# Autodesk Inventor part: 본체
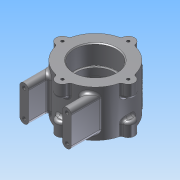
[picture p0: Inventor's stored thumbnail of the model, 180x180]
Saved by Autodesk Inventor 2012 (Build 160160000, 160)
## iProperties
Created: 2015-03
Part Number: 본체
Material: Default
Document SubType Name: Modeling
Designer: net
Density: 1 g/cm^3
Author: net
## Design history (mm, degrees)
sketch "스케치1"
  geometry: C1 r 37 at (0, 0); 1 further point
  constraints: 1 centre point, 1 coincident
  dimensions: "d0" = 74 diameter of C1
extrude "돌출1" new body sketch "스케치1" distance "d1" = 52; taper "d2" = 0 deg
hole "구멍1" diameter "d5" = 42; stored, may be unused: countersink angle "d9" = 90 deg, drill point angle "d11" = 0 deg; dims "d3" = 10, "d4" = 10, "d6" = 6, "d7" = 47, "d8" = 22, "d10" = 30
hole "구멍2" diameter "d14" = 47; stored, may be unused: countersink angle "d18" = 90 deg, drill point angle "d20" = 0 deg; dims "d12" = 10, "d13" = 10, "d15" = 6, "d16" = 47, "d17" = 22, "d19" = 22
sketch "스케치2"
  geometry: C1 r 23.5 at (0, 0) reference; C2 r 7 at (0, 37); 1 further point
  constraints: 1 centre point, 1 coincident, 1 vertical alignment
  dimensions: "d21" = 37 distance of point (0, 37) C1.centre; "d22" = 14 diameter of C2
extrude "돌출2" join sketch "스케치2" distance "d23" = 15; taper "d24" = 0 deg
hole "구멍3" diameter "d27" = 3.242; stored, may be unused: countersink angle "d31" = 90 deg, drill point angle "d33" = 118 deg; dims "d25" = 10, "d26" = 10, "d28" = 8, "d29" = 47, "d30" = 22, "d32" = 11
node "작업 평면1"
node "작업 평면2"
extrude "돌출3" join sketch "스케치4" stored distance "d41" = 15; taper "d42" = 0 deg
node "작업 평면3"
hole "구멍4" diameter "d46" = 4.134; stored, may be unused: countersink angle "d50" = 90 deg, drill point angle "d52" = 118 deg; dims "d44" = 10, "d45" = 10, "d47" = 6, "d48" = 47, "d49" = 22, "d51" = 8
hole "구멍5" diameter "d55" = 4.134; stored, may be unused: countersink angle "d59" = 90 deg, drill point angle "d61" = 118 deg; dims "d53" = 10, "d54" = 10, "d56" = 6, "d57" = 47, "d58" = 22, "d60" = 8
fillet "모깎기1" dims "d62" = 0.3
chamfer "모따기1" distance "d63" = 1; stored, may be unused: second distance "d64" = 2, angle "d65" = 45 deg
fillet "모깎기2" dims "d66" = 3
fillet "모깎기3" dims "d67" = 3
fillet "모깎기4" dims "d68" = 3
fillet "모깎기5" dims "d69" = 3
fillet "모깎기6" dims "d70" = 3
fillet "모깎기7" dims "d71" = 3
sketch "스케치5"
  geometry: L1 (29, -24)-(29, -56) reference; L2 (29, -56)-(19, -56) reference; L3 (19, -56)-(19, -36.661) reference; L4 (-19, -36.661)-(-19, -56) reference; L5 (-19, -56)-(-29, -56) reference; L6 (-29, -56)-(-29, -24) reference; L7 (0, 0)-(-26.163, 26.163); L8 (0, 0)-(-51.08, 0); C1 r 21 at (0, 0) reference; A1 r 37 centre (0, 0) between (29.6, -22.2) and (-29.6, -22.2) reference; A2 r 3 centre (32, -24) between (29.6, -22.2) and (29, -24) reference; A3 r 3 centre (16, -36.661) between (19, -36.661) and (14.8, -33.911) reference; A4 r 37 centre (0, 0) between (-14.8, -33.911) and (14.8, -33.911) reference; A5 r 3 centre (-16, -36.661) between (-14.8, -33.911) and (-19, -36.661) reference; A6 r 3 centre (-32, -24) between (-29, -24) and (-29.6, -22.2) reference; 1 further point
  constraints: 4 end point, 1 perpendicular, 1 point on circle
  dimensions: "d72" = 45 deg angle of L8 L7
  node "절단 모서리 투영2"
node "작업 평면4"
sketch "스케치6"
  geometry: L1 (23.5, -25)-(-23.5, -25) reference; L2 (-18.921, 26)-(18.921, 26) reference; 3 further points
  constraints: 1 coincident, 1 other
  dimensions: "d73" = 26 distance from line of L2 point (0, 0)
feature "엠보싱1" sketch "스케치6" dims "d1" = 52, "d31" = 90 deg, "d74" = 0.5, "d75" = 0
node "솔리드1"
pattern_circular "원형 패턴1" dims angle "d35" = 360 deg
mirror "대칭1"
mirror "대칭2"
mirror "대칭3"
other parameters: "d37" = -56, "d40" = 24, "d43" = 0
